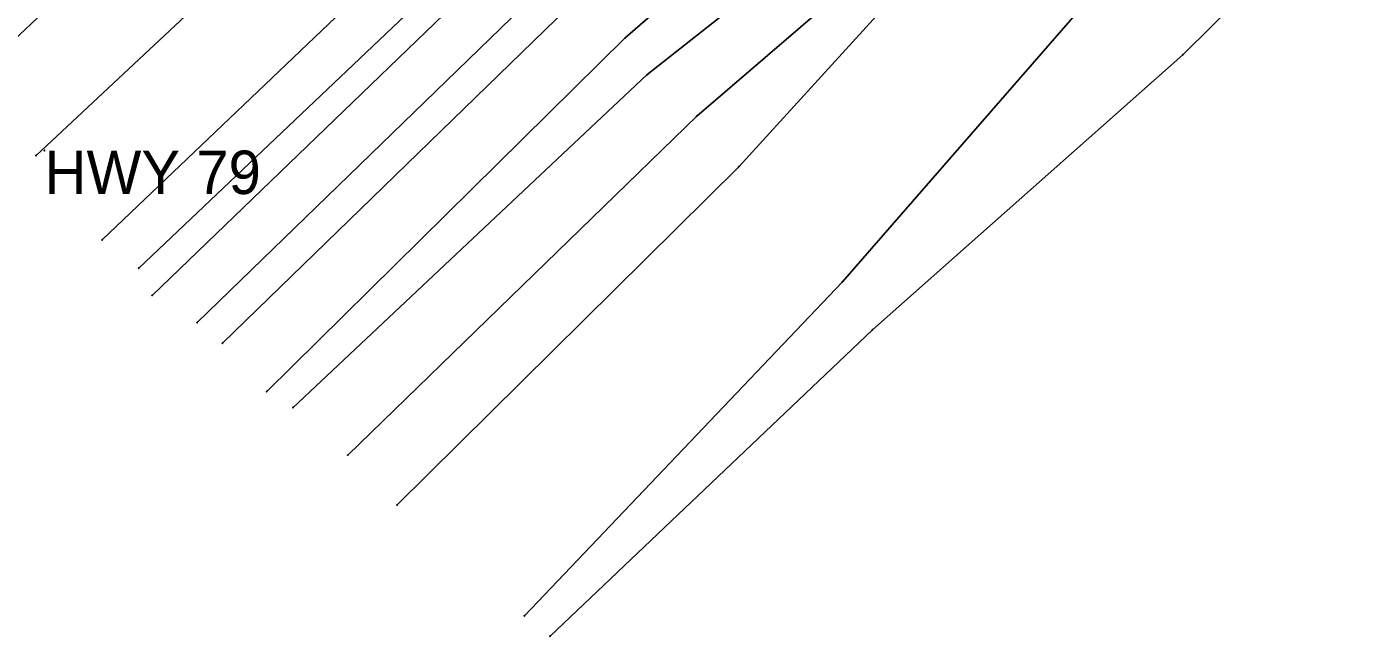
# Model space of a CAD drawing. Extents: x 1419505 to 1434054, y 1956910 to 1968644.
# Drawn here: x 1432529.3 to 1432681.8, y 1967044.6 to 1967114.9 of the extents above; entities that cross this region are included whole.
import ezdxf

# ---------------------------------------------------------------- set-up
doc = ezdxf.new("R2010")
doc.units = 0
for name, color, linetype in [('S_BREAKLINE', 7, 'Continuous'), ('S_DITCHLINE', 7, 'Continuous'), ('S_EDGE_PAVEMENT', 7, 'Continuous'), ('S_GRD_PT_SYM', 7, 'Continuous'), ('S_MSC_PT_SYM', 7, 'Continuous'), ('S_PAVEMENT_CROWN', 7, 'Continuous'), ('S_RDW_PT_SYM', 7, 'Continuous'), ('S_SHOULDER', 7, 'Continuous'), ('S_SURVEY_TEXT_ANNOT', 7, 'Continuous')]:
    doc.layers.add(name, color=color, linetype=linetype)

msp = doc.modelspace()

# ---------------------------------------------------------------- linework, layer by layer
at = {"layer": 'S_BREAKLINE'}
for p, q in [((1432693.7989, 1967142.7271), (1432662.3989, 1967111.5991)), ((1432637.4423, 1967138.3568), (1432600.7269, 1967109.3)), ((1432596.1826, 1967134.4326), (1432543.7782, 1967083.9183)), ((1432642.2756, 1967135.2736), (1432606.4443, 1967104.5466)), ((1432643.4087, 1967133.9795), (1432611.2926, 1967098.7163)), ((1432590.8333, 1967121.4087), (1432548.9606, 1967080.7991)), ((1432654.0264, 1967120.8287), (1432623.2214, 1967085.4774)), ((1432662.3989, 1967111.5991), (1432626.6686, 1967079.9451)), ((1432600.7269, 1967109.3), (1432559.9833, 1967071.0125)), ((1432606.4443, 1967104.5466), (1432566.2967, 1967065.5381)), ((1432611.2926, 1967098.7163), (1432571.9591, 1967059.7918)), ((1432623.2214, 1967085.4774), (1432586.61, 1967047.0389)), ((1432626.6686, 1967079.9451), (1432589.5642, 1967044.6988))]:
    msp.add_line(p, q, dxfattribs=at)
at = {"layer": 'S_DITCHLINE'}
for p, q in [((1432632.419, 1967143.5232), (1432598.2208, 1967113.5432)), ((1432593.1984, 1967118.5736), (1432551.8768, 1967078.41)), ((1432598.2208, 1967113.5432), (1432556.9571, 1967072.8476))]:
    msp.add_line(p, q, dxfattribs=at)
at = {"layer": 'S_EDGE_PAVEMENT'}
for p, q in [((1432576.4614, 1967159.2652), (1432522.6489, 1967108.3919)), ((1432591.8854, 1967141.659), (1432538.0259, 1967090.3057))]:
    msp.add_line(p, q, dxfattribs=at)
at = {"layer": 'S_GRD_PT_SYM'}
for points in [[(1432598.2208, 1967113.5432), (1432598.2208, 1967113.5932), (1432598.2208, 1967113.5432), (1432598.1708, 1967113.5432), (1432598.2208, 1967113.5432), (1432598.2208, 1967113.4932), (1432598.2208, 1967113.5432), (1432598.2708, 1967113.5432)], [(1432662.3989, 1967111.5991), (1432662.3989, 1967111.6491), (1432662.3989, 1967111.5991), (1432662.3489, 1967111.5991), (1432662.3989, 1967111.5991), (1432662.3989, 1967111.5491), (1432662.3989, 1967111.5991), (1432662.4489, 1967111.5991)], [(1432600.7269, 1967109.3), (1432600.7269, 1967109.35), (1432600.7269, 1967109.3), (1432600.6769, 1967109.3), (1432600.7269, 1967109.3), (1432600.7269, 1967109.25), (1432600.7269, 1967109.3), (1432600.7769, 1967109.3)], [(1432606.4443, 1967104.5466), (1432606.4443, 1967104.5966), (1432606.4443, 1967104.5466), (1432606.3943, 1967104.5466), (1432606.4443, 1967104.5466), (1432606.4443, 1967104.4966), (1432606.4443, 1967104.5466), (1432606.4943, 1967104.5466)], [(1432611.2926, 1967098.7163), (1432611.2926, 1967098.7663), (1432611.2926, 1967098.7163), (1432611.2426, 1967098.7163), (1432611.2926, 1967098.7163), (1432611.2926, 1967098.6663), (1432611.2926, 1967098.7163), (1432611.3426, 1967098.7163)], [(1432623.2214, 1967085.4774), (1432623.2214, 1967085.5274), (1432623.2214, 1967085.4774), (1432623.1714, 1967085.4774), (1432623.2214, 1967085.4774), (1432623.2214, 1967085.4274), (1432623.2214, 1967085.4774), (1432623.2714, 1967085.4774)], [(1432543.7782, 1967083.9183), (1432543.7782, 1967083.9683), (1432543.7782, 1967083.9183), (1432543.7282, 1967083.9183), (1432543.7782, 1967083.9183), (1432543.7782, 1967083.8683), (1432543.7782, 1967083.9183), (1432543.8282, 1967083.9183)], [(1432548.9606, 1967080.7991), (1432548.9606, 1967080.8491), (1432548.9606, 1967080.7991), (1432548.9106, 1967080.7991), (1432548.9606, 1967080.7991), (1432548.9606, 1967080.7491), (1432548.9606, 1967080.7991), (1432549.0106, 1967080.7991)], [(1432626.6686, 1967079.9451), (1432626.6686, 1967079.9951), (1432626.6686, 1967079.9451), (1432626.6186, 1967079.9451), (1432626.6686, 1967079.9451), (1432626.6686, 1967079.8951), (1432626.6686, 1967079.9451), (1432626.7186, 1967079.9451)], [(1432551.8768, 1967078.41), (1432551.8768, 1967078.46), (1432551.8768, 1967078.41), (1432551.8268, 1967078.41), (1432551.8768, 1967078.41), (1432551.8768, 1967078.36), (1432551.8768, 1967078.41), (1432551.9268, 1967078.41)], [(1432556.9571, 1967072.8476), (1432556.9571, 1967072.8976), (1432556.9571, 1967072.8476), (1432556.9071, 1967072.8476), (1432556.9571, 1967072.8476), (1432556.9571, 1967072.7976), (1432556.9571, 1967072.8476), (1432557.0071, 1967072.8476)], [(1432559.9833, 1967071.0125), (1432559.9833, 1967071.0625), (1432559.9833, 1967071.0125), (1432559.9333, 1967071.0125), (1432559.9833, 1967071.0125), (1432559.9833, 1967070.9625), (1432559.9833, 1967071.0125), (1432560.0333, 1967071.0125)], [(1432566.2967, 1967065.5381), (1432566.2967, 1967065.5881), (1432566.2967, 1967065.5381), (1432566.2467, 1967065.5381), (1432566.2967, 1967065.5381), (1432566.2967, 1967065.4881), (1432566.2967, 1967065.5381), (1432566.3467, 1967065.5381)], [(1432571.9591, 1967059.7918), (1432571.9591, 1967059.8418), (1432571.9591, 1967059.7918), (1432571.9091, 1967059.7918), (1432571.9591, 1967059.7918), (1432571.9591, 1967059.7418), (1432571.9591, 1967059.7918), (1432572.0091, 1967059.7918)], [(1432586.61, 1967047.0389), (1432586.61, 1967047.0889), (1432586.61, 1967047.0389), (1432586.56, 1967047.0389), (1432586.61, 1967047.0389), (1432586.61, 1967046.9889), (1432586.61, 1967047.0389), (1432586.66, 1967047.0389)], [(1432589.5642, 1967044.6988), (1432589.5642, 1967044.7488), (1432589.5642, 1967044.6988), (1432589.5142, 1967044.6988), (1432589.5642, 1967044.6988), (1432589.5642, 1967044.6488), (1432589.5642, 1967044.6988), (1432589.6142, 1967044.6988)]]:
    msp.add_lwpolyline(points, dxfattribs=at)
at = {"layer": 'S_MSC_PT_SYM'}
msp.add_lwpolyline([(1432531.3924, 1967100.5824), (1432531.3924, 1967100.6324), (1432531.3924, 1967100.5824), (1432531.3424, 1967100.5824), (1432531.3924, 1967100.5824), (1432531.3924, 1967100.5324), (1432531.3924, 1967100.5824), (1432531.4424, 1967100.5824)], dxfattribs=at)
at = {"layer": 'S_PAVEMENT_CROWN'}
msp.add_line((1432584.6329, 1967150.7456), (1432530.4184, 1967100.0134), dxfattribs=at)
at = {"layer": 'S_RDW_PT_SYM'}
for points in [[(1432530.4184, 1967100.0134), (1432530.4184, 1967100.0634), (1432530.4184, 1967100.0134), (1432530.3684, 1967100.0134), (1432530.4184, 1967100.0134), (1432530.4184, 1967099.9634), (1432530.4184, 1967100.0134), (1432530.4684, 1967100.0134)], [(1432538.0259, 1967090.3057), (1432538.0259, 1967090.3557), (1432538.0259, 1967090.3057), (1432537.9759, 1967090.3057), (1432538.0259, 1967090.3057), (1432538.0259, 1967090.2557), (1432538.0259, 1967090.3057), (1432538.0759, 1967090.3057)], [(1432542.2311, 1967087.0505), (1432542.2311, 1967087.1005), (1432542.2311, 1967087.0505), (1432542.1811, 1967087.0505), (1432542.2311, 1967087.0505), (1432542.2311, 1967087.0005), (1432542.2311, 1967087.0505), (1432542.2811, 1967087.0505)]]:
    msp.add_lwpolyline(points, dxfattribs=at)
at = {"layer": 'S_SHOULDER'}
msp.add_line((1432595.0026, 1967137.1207), (1432542.2311, 1967087.0505), dxfattribs=at)

# ---------------------------------------------------------------- texts
at = {"layer": 'S_SURVEY_TEXT_ANNOT'}
msp.add_text('HWY 79', height=5, dxfattribs=at).set_placement((1432531.3924, 1967095.5824))

doc.saveas('drawing.dxf')
